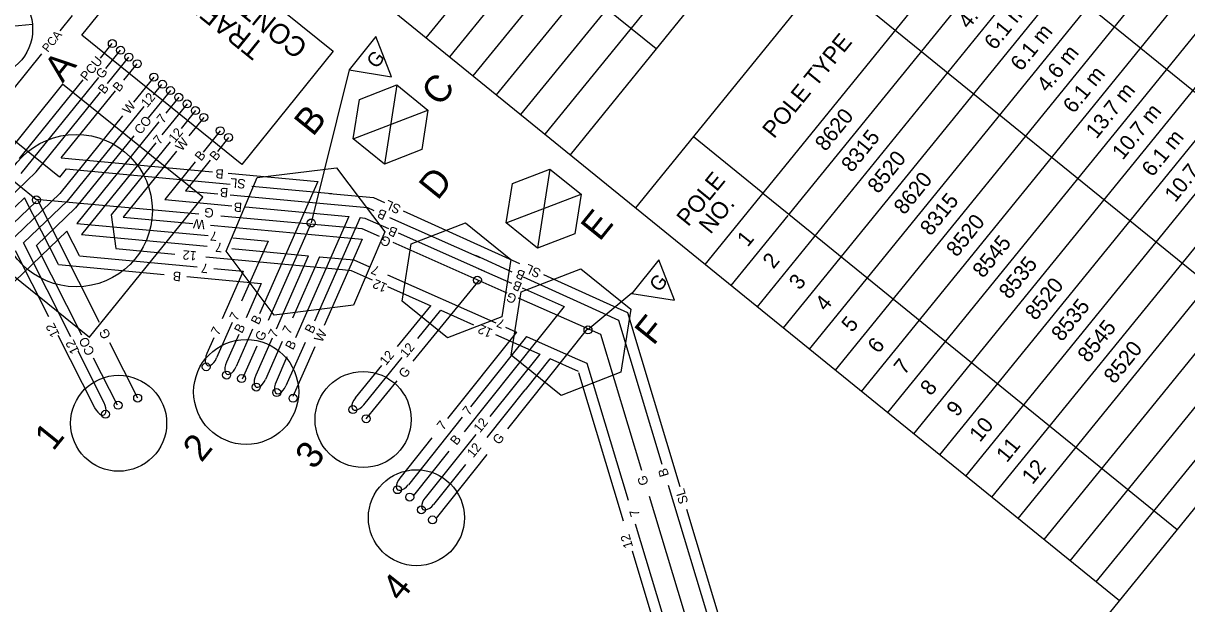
# Model space of a CAD drawing. Extents: x 592613 to 600223, y 4837996 to 4840103.
# Drawn here: x 592995.2 to 593036.62, y 4839219.91 to 4839240.59 of the extents above; entities that cross this region are included whole.
import ezdxf

# ---------------------------------------------------------------- set-up
doc = ezdxf.new("R2010")
doc.units = 0
for name, color, linetype in [('ENG_BORDER', 7, 'Continuous'), ('ENG_TITLEBLOCK', 7, 'Continuous'), ('ENG_TX_TITLEBLOCK', 7, 'Continuous'), ('Level 31', 7, 'Continuous'), ('Level 54', 7, 'Continuous'), ('TCS_CONTROLLER', 7, 'Continuous'), ('TCS_ELEC-CHAMBER-NEW', 7, 'Continuous'), ('TCS_PLATE', 7, 'Continuous'), ('TCS_POLE-EXIST', 7, 'Continuous'), ('TCS_POLE-NEW', 7, 'Continuous'), ('TCS_WR_12', 7, 'Continuous'), ('TCS_WR_7', 7, 'Continuous'), ('TCS_WR_B', 7, 'Continuous'), ('TCS_WR_CO', 7, 'Continuous'), ('TCS_WR_G', 7, 'Continuous'), ('TCS_WR_PCA', 7, 'Continuous'), ('TCS_WR_PCU', 7, 'Continuous'), ('TCS_WR_SL', 7, 'Continuous'), ('TCS_WR_W', 7, 'Continuous')]:
    doc.layers.add(name, color=color, linetype=linetype)

msp = doc.modelspace()

# ---------------------------------------------------------------- linework, layer by layer
at = {"layer": 'ENG_BORDER'}
for p, q in [((593034.225, 4839220.017), (592929.842, 4839304.827)), ((593017.004, 4839234.009), (593059.952, 4839286.868))]:
    msp.add_line(p, q, dxfattribs=at)
msp.add_lwpolyline([(593006.685, 4839186.123), (593132.065, 4839340.435), (593027.682, 4839425.246)], dxfattribs=at)
at = {"layer": 'ENG_TITLEBLOCK'}
msp.add_line((593014.678, 4839235.899), (593087.391, 4839325.585), dxfattribs=at)
at = {"layer": 'Level 31'}
for p, q in [((593019.478, 4839231.999), (593062.405, 4839284.832)), ((593022.481, 4839233.799), (593063.333, 4839284.078)), ((593021.335, 4839230.491), (593064.261, 4839283.324)), ((593022.263, 4839229.736), (593065.161, 4839282.536)), ((593023.19, 4839228.983), (593066.104, 4839281.799)), ((593024.118, 4839228.229), (593067.045, 4839281.062)), ((593025.046, 4839227.475), (593067.959, 4839280.291)), ((593025.974, 4839226.721), (593068.915, 4839279.571)), ((593026.902, 4839225.967), (593069.816, 4839278.782)), ((593027.831, 4839225.212), (593070.744, 4839278.029)), ((593028.759, 4839224.458), (593071.686, 4839277.292)), ((593029.686, 4839223.705), (593072.6, 4839276.52)), ((593030.615, 4839222.951), (593073.542, 4839275.784)), ((593031.543, 4839222.197), (593074.47, 4839275.029)), ((593032.471, 4839221.442), (593075.397, 4839274.276)), ((593033.399, 4839220.689), (593076.325, 4839273.521)), ((593017.738, 4839239.673), (593000.216, 4839253.911)), ((593009.548, 4839240.067), (593019.664, 4839252.515)), ((593010.384, 4839239.388), (593020.517, 4839251.857)), ((593011.219, 4839238.71), (593021.299, 4839251.114)), ((593012.054, 4839238.031), (593022.134, 4839250.436)), ((593012.054, 4839238.031), (593022.134, 4839250.435)), ((593012.917, 4839237.331), (593022.997, 4839249.735)), ((593013.779, 4839236.63), (593023.859, 4839249.034)), ((593044.257, 4839232.156), (593026.95, 4839246.219)), ((593041.095, 4839228.264), (593023.773, 4839242.338)), ((593020.406, 4839231.245), (593022.428, 4839233.734))]:
    msp.add_line(p, q, dxfattribs=at)
at = {"layer": 'Level 54'}
for p, q in [((593040.993, 4839228.347), (593023.773, 4839242.338)), ((593021.525, 4839234.529), (593019.056, 4839236.535)), ((593021.53, 4839234.525), (593021.525, 4839234.529)), ((593022.458, 4839233.771), (593021.53, 4839234.525)), ((593036.277, 4839222.543), (593022.458, 4839233.771))]:
    msp.add_line(p, q, dxfattribs=at)
at = {"layer": 'TCS_CONTROLLER'}
msp.add_lwpolyline([(593000.545, 4839244.191), (593006.239, 4839239.592), (593002.982, 4839235.56), (592997.288, 4839240.159)], close=True, dxfattribs=at)
at = {"layer": 'TCS_ELEC-CHAMBER-NEW'}
for p, q in [((592996.605, 4839238.421), (592992.576, 4839233.433)), ((593001.593, 4839234.393), (592996.605, 4839238.421)), ((593007.171, 4839237.875), (593008.501, 4839238.388)), ((593008.501, 4839238.388), (593008.059, 4839235.572)), ((593008.501, 4839238.388), (593009.61, 4839237.492)), ((593006.95, 4839236.468), (593007.171, 4839237.875)), ((593006.95, 4839236.468), (593009.61, 4839237.492)), ((593009.61, 4839237.492), (593009.389, 4839236.085)), ((593008.059, 4839235.572), (593006.95, 4839236.468)), ((593009.389, 4839236.085), (593008.059, 4839235.572)), ((593003.534, 4839235.087), (593006.359, 4839235.434)), ((593006.359, 4839235.434), (593008.071, 4839233.161)), ((593012.619, 4839234.883), (593013.949, 4839235.395)), ((593013.949, 4839235.395), (593013.507, 4839232.58)), ((593013.949, 4839235.395), (593015.057, 4839234.5)), ((593002.421, 4839232.468), (593003.534, 4839235.087)), ((593012.398, 4839233.475), (593012.619, 4839234.883)), ((593012.398, 4839233.475), (593015.057, 4839234.5)), ((593015.057, 4839234.5), (593014.836, 4839233.092)), ((592997.564, 4839229.404), (593001.593, 4839234.393)), ((592992.576, 4839233.433), (592997.564, 4839229.404)), ((593009.016, 4839232.729), (593010.947, 4839233.473)), ((593010.947, 4839233.473), (593012.557, 4839232.173)), ((593013.507, 4839232.58), (593012.398, 4839233.475)), ((593008.071, 4839233.161), (593006.959, 4839230.541)), ((593014.836, 4839233.092), (593013.507, 4839232.58)), ((593004.134, 4839230.195), (593002.421, 4839232.468)), ((593008.695, 4839230.685), (593009.016, 4839232.729)), ((593012.557, 4839232.173), (593012.235, 4839230.129)), ((593012.925, 4839231.019), (593015.053, 4839231.839)), ((593015.053, 4839231.839), (593016.827, 4839230.406)), ((593012.572, 4839228.767), (593012.925, 4839231.019)), ((593006.959, 4839230.541), (593004.134, 4839230.195)), ((593010.305, 4839229.385), (593008.695, 4839230.685)), ((593016.827, 4839230.406), (593016.473, 4839228.154)), ((593012.235, 4839230.129), (593010.305, 4839229.385)), ((593014.345, 4839227.334), (593012.572, 4839228.767)), ((593016.473, 4839228.154), (593014.345, 4839227.334))]:
    msp.add_line(p, q, dxfattribs=at)
msp.add_circle((592997.085, 4839233.914), 2.715, dxfattribs=at)
at = {"layer": 'TCS_PLATE'}
for p, q in [((593007.759, 4839240.113), (593006.799, 4839238.925)), ((593008.316, 4839238.681), (593007.759, 4839240.113)), ((593006.799, 4839238.925), (593008.316, 4839238.681)), ((593017.832, 4839232.159), (593016.865, 4839230.962)), ((593018.386, 4839230.724), (593017.832, 4839232.159)), ((593016.865, 4839230.962), (593018.386, 4839230.724))]:
    msp.add_line(p, q, dxfattribs=at)
at = {"layer": 'TCS_POLE-EXIST'}
msp.add_line((592995.529, 4839240.546), (592992.127, 4839240.2), dxfattribs=at)
msp.add_circle((592993.828, 4839240.374), 1.71, dxfattribs=at)
at = {"layer": 'TCS_POLE-NEW'}
for centre, radius in [((593003.138, 4839227.455), 1.869), ((592998.598, 4839226.34), 1.71), ((593007.301, 4839226.473), 1.71), ((593009.198, 4839222.976), 1.71)]:
    msp.add_circle(centre, radius, dxfattribs=at)
at = {"layer": 'TCS_WR_12'}
for p, q in [((593000.127, 4839238.401), (592999.83, 4839238.034)), ((592999.496, 4839237.62), (592996.772, 4839234.248)), ((593001.331, 4839237.473), (593000.821, 4839236.842)), ((593000.431, 4839236.359), (592998.332, 4839233.76)), ((592996.779, 4839234.265), (592995.212, 4839232.76)), ((592998.332, 4839233.76), (592998.497, 4839232.564)), ((592996.111, 4839230.135), (592994.926, 4839232.484)), ((592996.901, 4839229.413), (592995.212, 4839232.76)), ((592998.497, 4839232.564), (593000.599, 4839232.368)), ((593001.703, 4839232.265), (593006.569, 4839231.812)), ((593006.569, 4839231.812), (593006.871, 4839231.784)), ((593006.871, 4839231.784), (593007.627, 4839231.449)), ((593008.164, 4839231.21), (593009.711, 4839230.524)), ((593008.525, 4839229.072), (593009.711, 4839230.524)), ((593009.246, 4839229.355), (593010.071, 4839230.365)), ((593010.071, 4839230.365), (593011.234, 4839229.849)), ((592997.747, 4839226.892), (592996.446, 4839229.47)), ((593012.01, 4839229.505), (593013.59, 4839228.804)), ((592998.087, 4839227.063), (592997.158, 4839228.904)), ((593007.324, 4839227), (593008.697, 4839228.682)), ((593013.59, 4839228.804), (593011.815, 4839226.577)), ((593013.952, 4839228.643), (593014.955, 4839228.199)), ((593007.029, 4839227.24), (593007.97, 4839228.393)), ((593013.944, 4839228.634), (593013.065, 4839227.533)), ((593014.968, 4839228.153), (593016.56, 4839222.86)), ((593013.063, 4839227.534), (593011.708, 4839225.834)), ((593011.308, 4839225.942), (593009.505, 4839223.68)), ((593010.942, 4839224.873), (593009.802, 4839223.443)), ((593016.88, 4839221.797), (593018.188, 4839217.447))]:
    msp.add_line(p, q, dxfattribs=at)
for centre, major_axis in [((592997.914, 4839226.98), (-0.171, 0.339)), ((593007.176, 4839227.12), (0.24, 0.294)), ((593009.66, 4839223.571), (0.237, 0.297))]:
    msp.add_ellipse(centre, major_axis=major_axis, ratio=0.5, start_param=1.570796, end_param=4.712389, dxfattribs=at)
at = {"layer": 'TCS_WR_7'}
for p, q in [((593000.739, 4839237.951), (593000.284, 4839237.387)), ((593001.035, 4839237.712), (593000.142, 4839236.607)), ((593000.03, 4839237.072), (592997.109, 4839233.456)), ((592999.918, 4839236.329), (592997.277, 4839233.059)), ((592997.109, 4839233.456), (593001.785, 4839233.021)), ((592996.76, 4839233.187), (592992.648, 4839229.235)), ((592997.207, 4839232.302), (592996.76, 4839233.187)), ((592997.277, 4839233.059), (593001.75, 4839232.642)), ((593002.661, 4839232.939), (593003.919, 4839232.822)), ((593003.919, 4839232.822), (593002.977, 4839230.685)), ((593002.626, 4839232.561), (593005.353, 4839232.307)), ((592997.207, 4839232.302), (593001.393, 4839231.912)), ((593005.347, 4839232.294), (593004.202, 4839229.697)), ((593005.751, 4839232.27), (593004.789, 4839230.085)), ((593005.751, 4839232.27), (593006.969, 4839232.156)), ((593006.969, 4839232.156), (593007.523, 4839231.91)), ((593001.984, 4839231.857), (593003.035, 4839231.759)), ((593003.035, 4839231.759), (593002.285, 4839230.057)), ((593008.173, 4839231.622), (593012.024, 4839229.914)), ((593002.645, 4839229.932), (593002.088, 4839228.668)), ((593012.757, 4839229.589), (593010.3, 4839226.506)), ((593012.367, 4839229.762), (593012.757, 4839229.589)), ((593001.987, 4839229.38), (593001.74, 4839228.821)), ((593004.06, 4839229.374), (593003.479, 4839228.055)), ((593004.421, 4839229.252), (593003.826, 4839227.901)), ((593013.116, 4839229.43), (593011.118, 4839226.923)), ((593013.116, 4839229.43), (593014.844, 4839228.663)), ((593014.844, 4839228.663), (593015.268, 4839228.475)), ((593015.268, 4839228.475), (593016.736, 4839223.596)), ((593010.83, 4839226.561), (593008.911, 4839224.153)), ((593009.753, 4839225.82), (593008.613, 4839224.39)), ((593016.989, 4839222.753), (593018.261, 4839218.525)), ((593016.989, 4839222.753), (593018.566, 4839217.509))]:
    msp.add_line(p, q, dxfattribs=at)
for centre, major_axis in [((593001.914, 4839228.744), (0.153, 0.348)), ((593003.651, 4839227.978), (0.153, 0.348)), ((593008.762, 4839224.271), (0.237, 0.297))]:
    msp.add_ellipse(centre, major_axis=major_axis, ratio=0.5, start_param=1.570796, end_param=4.712389, dxfattribs=at)
at = {"layer": 'TCS_WR_B'}
for p, q in [((592998.204, 4839238.44), (592998.966, 4839239.383)), ((592998.788, 4839238.559), (592999.261, 4839239.144)), ((592996.558, 4839235.797), (592998.486, 4839238.184)), ((592995.666, 4839235.298), (592997.956, 4839238.133)), ((593002.217, 4839236.757), (593001.604, 4839235.997)), ((593002.513, 4839236.518), (593002.114, 4839236.023)), ((592996.558, 4839235.797), (593001.944, 4839235.296)), ((593001.855, 4839235.704), (593000.982, 4839234.622)), ((592995.666, 4839235.298), (592990.147, 4839229.994)), ((593001.321, 4839235.646), (593000.241, 4839234.309)), ((593002.501, 4839235.244), (593005.686, 4839234.947)), ((593005.686, 4839234.947), (593003.607, 4839230.233)), ((593000.982, 4839234.622), (593002.134, 4839234.515)), ((593002.569, 4839234.474), (593005.363, 4839234.214)), ((592995.25, 4839234.373), (592991.061, 4839230.345)), ((592996.452, 4839231.991), (592995.25, 4839234.373)), ((593000.241, 4839234.309), (593002.629, 4839234.087)), ((593003.109, 4839234.042), (593006.792, 4839233.699)), ((593005.363, 4839234.214), (593007.454, 4839234.019)), ((593006.792, 4839233.699), (593004.89, 4839229.382)), ((593007.191, 4839233.662), (593005.567, 4839229.977)), ((593007.191, 4839233.662), (593007.357, 4839233.647)), ((593007.357, 4839233.647), (593008.201, 4839233.272)), ((593007.454, 4839234.019), (593007.681, 4839233.918)), ((593008.236, 4839233.673), (593011.452, 4839232.246)), ((593008.544, 4839233.12), (593011.62, 4839231.756)), ((592996.452, 4839231.991), (593000.219, 4839231.64)), ((593011.298, 4839232.322), (593012.598, 4839231.734)), ((593001.023, 4839231.565), (593003.675, 4839231.318)), ((593011.399, 4839231.854), (593012.581, 4839231.33)), ((593013.004, 4839231.55), (593015.166, 4839230.572)), ((593003.675, 4839231.318), (593003.135, 4839230.097)), ((593012.966, 4839231.159), (593014.455, 4839230.499)), ((593014.455, 4839230.499), (593010.894, 4839226.032)), ((593015.166, 4839230.572), (593016.397, 4839230.015)), ((593016.397, 4839230.015), (593017.94, 4839224.881)), ((593002.873, 4839229.505), (593002.435, 4839228.514)), ((593003.369, 4839229.691), (593002.782, 4839228.361)), ((593005.234, 4839229.221), (593004.549, 4839227.668)), ((593004.589, 4839228.7), (593004.202, 4839227.821)), ((593010.348, 4839225.347), (593009.09, 4839223.768)), ((593018.163, 4839224.138), (593019.778, 4839218.765))]:
    msp.add_line(p, q, dxfattribs=at)
for centre in [(593002.608, 4839228.437), (593004.375, 4839227.744)]:
    msp.add_ellipse(centre, major_axis=(0.153, 0.348), ratio=0.5, start_param=1.570796, end_param=4.712389, dxfattribs=at)
at = {"layer": 'TCS_WR_CO'}
for p, q in [((593000.444, 4839238.189), (592999.655, 4839237.212)), ((592999.14, 4839236.576), (592997.067, 4839234.009)), ((592997.067, 4839234.009), (592995.68, 4839232.676)), ((592997.292, 4839229.481), (592995.68, 4839232.676)), ((592998.554, 4839226.98), (592997.708, 4839228.656))]:
    msp.add_line(p, q, dxfattribs=at)
at = {"layer": 'TCS_WR_G'}
for p, q in [((592998.148, 4839238.976), (592998.67, 4839239.622)), ((592995.125, 4839235.232), (592997.888, 4839238.653)), ((593006.799, 4839238.925), (593005.455, 4839233.472)), ((592995.687, 4839234.29), (592993.325, 4839236.198)), ((592995.662, 4839234.243), (592990.696, 4839229.467)), ((592995.653, 4839234.317), (593001.457, 4839233.796)), ((592997.919, 4839229.927), (592995.706, 4839234.313)), ((593002.233, 4839233.726), (593007.26, 4839233.274)), ((593005.436, 4839233.438), (593003.918, 4839229.994)), ((593007.26, 4839233.274), (593007.873, 4839233.002)), ((593008.362, 4839232.785), (593012.42, 4839230.986)), ((593009.077, 4839228.546), (593011.428, 4839231.426)), ((593012.825, 4839230.806), (593015.751, 4839229.508)), ((593016.871, 4839230.97), (593015.306, 4839229.665)), ((593015.293, 4839229.711), (593012.437, 4839226.14)), ((593015.751, 4839229.508), (593017.206, 4839224.67)), ((592999.276, 4839227.237), (592998.28, 4839229.21)), ((593003.52, 4839229.091), (593002.997, 4839227.905)), ((593007.408, 4839226.503), (593008.512, 4839227.855)), ((593011.707, 4839225.227), (593009.9, 4839222.962)), ((593017.483, 4839223.749), (593019.448, 4839217.214))]:
    msp.add_line(p, q, dxfattribs=at)
at = {"layer": 'TCS_WR_PCA'}
for p, q in [((592996.521, 4839240.316), (592996.959, 4839240.858)), ((592994.298, 4839237.565), (592995.859, 4839239.497))]:
    msp.add_line(p, q, dxfattribs=at)
at = {"layer": 'TCS_WR_PCU'}
for p, q in [((592997.951, 4839239.337), (592998.374, 4839239.861)), ((592995.068, 4839235.767), (592997.337, 4839238.576))]:
    msp.add_line(p, q, dxfattribs=at)
at = {"layer": 'TCS_WR_SL'}
for p, q in [((592996.489, 4839235.107), (592994.637, 4839236.603)), ((592996.727, 4839235.402), (592996.489, 4839235.107)), ((592996.727, 4839235.4), (593002.571, 4839234.856)), ((593003.338, 4839234.784), (593006.193, 4839234.518)), ((593006.103, 4839234.527), (593007.67, 4839234.381)), ((593007.67, 4839234.381), (593008.063, 4839234.203)), ((593008.721, 4839233.905), (593012.871, 4839232.027)), ((593013.725, 4839231.641), (593016.711, 4839230.29)), ((593016.711, 4839230.29), (593018.575, 4839224.088)), ((593018.818, 4839223.28), (593020.593, 4839217.373))]:
    msp.add_line(p, q, dxfattribs=at)
at = {"layer": 'TCS_WR_W'}
for p, q in [((592999.852, 4839238.667), (592999.133, 4839237.776)), ((592998.736, 4839237.284), (592996.508, 4839234.525)), ((593001.626, 4839237.234), (593001.099, 4839236.581)), ((593000.655, 4839236.032), (592998.759, 4839233.684)), ((592996.508, 4839234.525), (592991.532, 4839229.744)), ((592998.759, 4839233.684), (593001.239, 4839233.453)), ((593001.873, 4839233.394), (593007.267, 4839232.892)), ((593007.267, 4839232.892), (593005.915, 4839229.824)), ((593005.581, 4839229.067), (593004.802, 4839227.299))]:
    msp.add_line(p, q, dxfattribs=at)
for centre in [(592998.374, 4839239.861), (592998.67, 4839239.622), (592998.966, 4839239.383), (592999.261, 4839239.144), (592999.852, 4839238.667), (593000.161, 4839238.414), (593000.444, 4839238.189), (593000.739, 4839237.951), (593001.035, 4839237.712), (593001.331, 4839237.473), (593001.626, 4839237.234), (593002.217, 4839236.757), (593002.513, 4839236.518), (592995.67, 4839234.296), (593005.455, 4839233.472), (593011.368, 4839231.436), (593015.306, 4839229.665), (593001.714, 4839228.35), (593002.442, 4839228.056), (593002.973, 4839227.933), (593003.498, 4839227.63), (593004.225, 4839227.435), (592998.578, 4839226.981), (592999.276, 4839227.237), (593004.81, 4839227.231), (592998.131, 4839226.66), (593006.936, 4839226.826), (593007.408, 4839226.503), (593008.524, 4839223.975), (593008.96, 4839223.709), (593009.376, 4839223.257), (593009.771, 4839222.9)]:
    msp.add_circle(centre, 0.142, dxfattribs=at)

# ---------------------------------------------------------------- texts
at = {"layer": 'ENG_TX_TITLEBLOCK'}
for s, height, rotation, p in [('4.6 m', 0.55, 51.1458, (593028.854, 4839240.353)), ('6.1 m', 0.55, 51.1458, (593029.788, 4839239.6)), ('POLE TYPE', 0.6, 50.9062, (593021.926, 4839236.449)), ('6.1 m', 0.55, 51.1458, (593030.723, 4839238.847)), ('4.6 m', 0.55, 51.1458, (593031.657, 4839238.094)), ('6.1 m', 0.55, 51.1458, (593032.592, 4839237.342)), ('13.7 m', 0.55, 51.1458, (593033.406, 4839236.44)), ('8620', 0.55, 51.1458, (593023.764, 4839235.993)), ('10.7 m', 0.55, 51.1458, (593034.341, 4839235.687)), ('8315', 0.55, 51.1458, (593024.7, 4839235.242)), ('6.1 m', 0.55, 51.1458, (593035.395, 4839235.083)), ('10.7 m', 0.55, 51.1458, (593036.21, 4839234.181)), ('8520', 0.55, 51.1458, (593025.633, 4839234.487)), ('POLE', 0.6, 50.9062, (593018.873, 4839233.315)), ('8620', 0.55, 51.1458, (593026.567, 4839233.734)), ('8315', 0.55, 51.1458, (593027.503, 4839232.983)), ('NO.', 0.6, 50.9062, (593019.667, 4839233.046)), ('8520', 0.55, 51.1458, (593028.436, 4839232.229)), ('1', 0.55, 51.1458, (593020.992, 4839232.59)), ('8545', 0.55, 51.1458, (593029.372, 4839231.478)), ('2', 0.55, 51.1458, (593021.905, 4839231.809)), ('8535', 0.55, 51.1458, (593030.307, 4839230.725)), ('3', 0.55, 51.1458, (593022.839, 4839231.056)), ('8520', 0.55, 51.1458, (593031.24, 4839229.97)), ('4', 0.55, 51.1458, (593023.771, 4839230.301)), ('8535', 0.55, 51.1458, (593032.176, 4839229.219)), ('5', 0.55, 51.1458, (593024.707, 4839229.55)), ('8545', 0.55, 51.1458, (593033.11, 4839228.466)), ('6', 0.55, 51.1458, (593025.64, 4839228.794)), ('8520', 0.55, 51.1458, (593034.043, 4839227.712)), ('7', 0.55, 51.1458, (593026.57, 4839228.036)), ('8', 0.55, 51.1458, (593027.51, 4839227.29)), ('9', 0.55, 51.1458, (593028.446, 4839226.539)), ('10', 0.55, 51.1458, (593029.258, 4839225.635)), ('11', 0.55, 51.1458, (593030.217, 4839224.912)), ('12', 0.55, 51.1458, (593031.129, 4839224.132))]:
    msp.add_text(s, height=height, rotation=rotation, dxfattribs=at).set_placement(p)
at = {"layer": 'TCS_CONTROLLER'}
for s, p in [('CONTROLLER', (593005.378, 4839239.824)), ('TRAFFIC', (593003.826, 4839239.795))]:
    msp.add_text(s, height=0.7125, rotation=141.0744, dxfattribs=at).set_placement(p)
at = {"layer": 'TCS_ELEC-CHAMBER-NEW'}
for s, p in [('A', (592996.605, 4839238.434)), ('C', (593010.039, 4839237.585)), ('B', (593005.512, 4839236.521)), ('D', (593009.954, 4839234.25)), ('E', (593015.718, 4839232.788)), ('F', (593017.634, 4839229.077))]:
    msp.add_text(s, height=0.95, rotation=51.0744, dxfattribs=at).set_placement(p)
at = {"layer": 'TCS_PLATE'}
for p in [(593007.775, 4839238.939), (593017.844, 4839230.98)]:
    msp.add_text('G', height=0.513, rotation=51.0744, dxfattribs=at).set_placement(p)
at = {"layer": 'TCS_POLE-NEW'}
for s, p in [('1', (592996.267, 4839225.322)), ('2', (593001.546, 4839224.915)), ('3', (593005.546, 4839224.654)), ('4', (593008.639, 4839219.942))]:
    msp.add_text(s, height=0.95, rotation=51.0744, dxfattribs=at).set_placement(p)
at = {"layer": 'TCS_WR_12'}
for rotation, p in [(51.0744, (592999.616, 4839237.556)), (51.0744, (593000.601, 4839236.305)), (174.6781, (593001.388, 4839232.461)), (156.0833, (593008.19, 4839231.286)), (116.468, (592996.505, 4839229.502)), (156.0833, (593011.937, 4839229.674)), (116.468, (592997.209, 4839228.908)), (50.77, (593008.843, 4839228.652)), (50.77, (593008.115, 4839228.378)), (51.3479, (593011.46, 4839225.978)), (51.3479, (593011.222, 4839225.089)), (106.7383, (593016.915, 4839221.946))]:
    msp.add_text('12', height=0.3325, rotation=rotation, dxfattribs=at).set_placement(p)
at = {"layer": 'TCS_WR_7'}
for height, rotation, p in [(0.332, 51.0744, (593000.181, 4839236.995)), (0.333, 51.0744, (593000.059, 4839236.238)), (0.333, 174.6781, (593002.122, 4839233.16)), (0.333, 174.6781, (593002.31, 4839232.757)), (0.333, 174.6781, (593001.8, 4839232.013)), (0.332, 156.0833, (593007.91, 4839231.891)), (0.332, 62.6356, (593002.814, 4839229.96)), (0.332, 156.0833, (593012.379, 4839229.997)), (0.332, 62.6356, (593002.156, 4839229.441)), (0.332, 62.6356, (593004.197, 4839229.358)), (0.332, 62.6356, (593004.7, 4839229.485)), (0.333, 51.3479, (593011.068, 4839226.592)), (0.333, 51.3479, (593010.154, 4839226.071)), (0.333, 106.7383, (593017.159, 4839223.068))]:
    msp.add_text('7', height=height, rotation=rotation, dxfattribs=at).set_placement(p)
at = {"layer": 'TCS_WR_B'}
for height, rotation, p in [(0.333, 51.0744, (592998.089, 4839238.039)), (0.333, 51.0744, (592998.615, 4839238.115)), (0.333, 51.0744, (593001.535, 4839235.652)), (0.333, 51.0744, (593002.063, 4839235.661)), (0.332, 174.6781, (593002.352, 4839235.374)), (0.332, 174.6781, (593002.512, 4839234.71)), (0.332, 174.6781, (593003.005, 4839234.185)), (0.333, 156.0833, (593008.171, 4839233.87)), (0.333, 156.0833, (593008.558, 4839233.255)), (0.332, 174.6781, (593000.835, 4839231.723)), (0.333, 156.0833, (593013.1, 4839231.723)), (0.332, 156.0833, (593012.987, 4839231.319)), (0.332, 62.6356, (593002.986, 4839229.517)), (0.332, 62.6356, (593003.58, 4839229.822)), (0.332, 62.6356, (593005.498, 4839229.508)), (0.332, 62.6356, (593004.804, 4839228.927)), (0.333, 51.3479, (593010.627, 4839225.532)), (0.333, 106.7383, (593018.193, 4839224.488))]:
    msp.add_text('B', height=height, rotation=rotation, dxfattribs=at).set_placement(p)
at = {"layer": 'TCS_WR_CO'}
for rotation, p in [(51.0744, (592999.382, 4839236.599)), (116.468, (592997.759, 4839228.855))]:
    msp.add_text('CO', height=0.3325, rotation=rotation, dxfattribs=at).set_placement(p)
at = {"layer": 'TCS_WR_G'}
for height, rotation, p in [(0.333, 51.0744, (592998.012, 4839238.581)), (0.332, 174.6781, (593001.999, 4839233.986)), (0.332, 156.0833, (593008.325, 4839232.901)), (0.332, 156.0833, (593012.802, 4839230.882)), (0.333, 116.468, (592998.332, 4839229.446)), (0.332, 62.6356, (593003.727, 4839229.237)), (0.333, 50.77, (593008.791, 4839227.917)), (0.333, 51.3479, (593012.138, 4839225.553)), (0.333, 106.7383, (593017.469, 4839224.183))]:
    msp.add_text('G', height=height, rotation=rotation, dxfattribs=at).set_placement(p)
at = {"layer": 'TCS_WR_PCA'}
msp.add_text('PCA', height=0.2993, rotation=51.0574, dxfattribs=at).set_placement((592996.08, 4839239.532))
at = {"layer": 'TCS_WR_PCU'}
msp.add_text('PCU', height=0.3325, rotation=51.0744, dxfattribs=at).set_placement((592997.461, 4839238.505))
at = {"layer": 'TCS_WR_SL'}
for rotation, p in [(174.6781, (593003.132, 4839235.022)), (156.0833, (593008.678, 4839234.081)), (156.0833, (593013.663, 4839231.804)), (106.7383, (593018.879, 4839223.522))]:
    msp.add_text('SL', height=0.3325, rotation=rotation, dxfattribs=at).set_placement(p)
at = {"layer": 'TCS_WR_W'}
for height, rotation, p in [(0.333, 51.0744, (592998.962, 4839237.318)), (0.333, 51.0744, (593000.847, 4839236.005)), (0.333, 174.6781, (593001.686, 4839233.573)), (0.332, 62.6356, (593005.835, 4839229.196))]:
    msp.add_text('W', height=height, rotation=rotation, dxfattribs=at).set_placement(p)

doc.saveas('drawing.dxf')
